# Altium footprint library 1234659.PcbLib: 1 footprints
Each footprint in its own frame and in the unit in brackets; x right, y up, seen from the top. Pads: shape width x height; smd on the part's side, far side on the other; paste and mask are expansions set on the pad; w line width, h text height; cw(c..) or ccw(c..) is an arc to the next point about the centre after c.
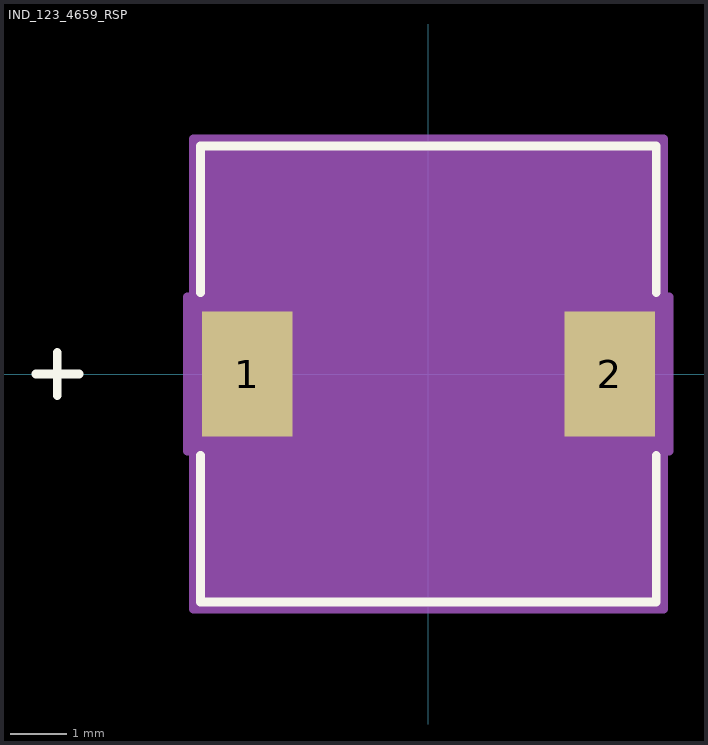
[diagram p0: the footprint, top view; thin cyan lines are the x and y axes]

## IND_123_4659_RSP [mil]
pads (2):
  rect 63x87 smd paste+0 mask+0: 1(-126,0) 2(126,0)
Top Overlay:
  lines w6: -273,0 -243,0 ; -258,-15 -258,15 ; -158.5,-56.56 -158.5,-158.5 158.5,-158.5 158.5,-56.56 ; -158.5,56.56 -158.5,158.5 158.5,158.5 158.5,56.56
Mechanical 5:
  region: 165,-161 -165,-161 -165,161 165,161
Mechanical 13:
  lines w1: -273,0 -243,0 ; -258,-15 -258,15 ; -153.5,-153.5 153.5,-153.5 153.5,153.5 -153.5,153.5 -153.5,-153.5
Mechanical 15:
  region: -163.5,-53.5 -167.5,-53.5 -167.5,53.5 -163.5,53.5 -163.5,163.5 163.5,163.5 163.5,53.5 167.5,53.5 167.5,-53.5 163.5,-53.5 163.5,-163.5 -163.5,-163.5
  lines w6: -167.5,-53.5 -167.5,53.5 -163.5,53.5 -163.5,163.5 163.5,163.5 163.5,53.5 167.5,53.5 167.5,-53.5 163.5,-53.5 163.5,-163.5 -163.5,-163.5 -163.5,-53.5 -167.5,-53.5
3D body "IND_123_4659_RSP.step": height 199.02, standoff 0, extent -153.5,-153.5 153.5,153.5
